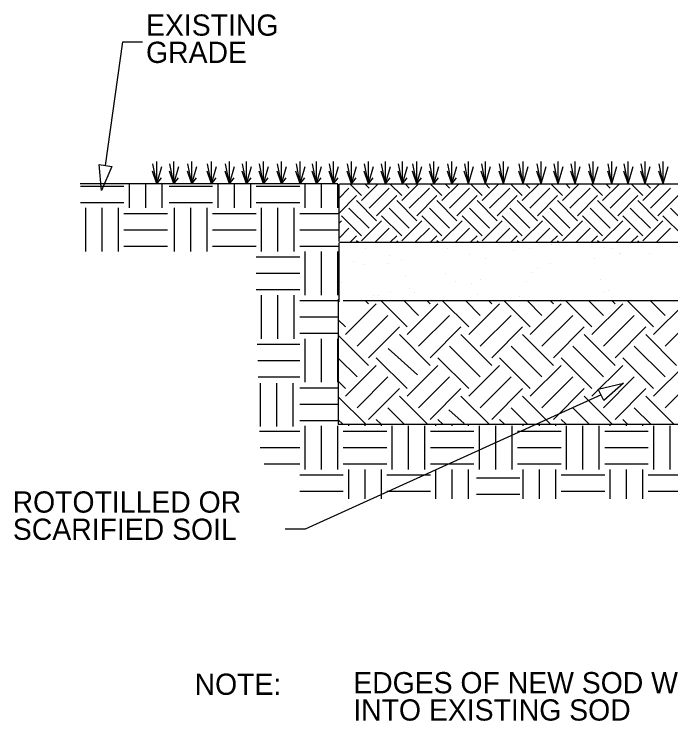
# Model space of a CAD drawing. Extents: x 10146.6 to 10186.7, y 9955.2 to 10001.8.
# Drawn here: x 10146.58 to 10168.25, y 9978.52 to 10001.83 of the extents above; entities that cross this region are included whole.
import ezdxf

# ---------------------------------------------------------------- set-up
doc = ezdxf.new("R2010")
doc.units = 0
for name, color, linetype in [('Default', 7, 'Continuous'), ('G-DETL-OTLN', 7, 'Continuous'), ('G-DETL-PATT', 7, 'Continuous'), ('G-DETL-TEXT', 7, 'Continuous')]:
    doc.layers.add(name, color=color, linetype=linetype)

# ---------------------------------------------------------------- blocks, each defined once
blk = doc.blocks.new('TERARR')
at = {"layer": 'Default'}
blk.add_lwpolyline([(-0.667, 0.167), (0, 0), (-0.667, -0.167)], close=True, dxfattribs=at)

msp = doc.modelspace()

# ---------------------------------------------------------------- linework, layer by layer
at = {"layer": 'G-DETL-OTLN'}
for points in [[(10157.298, 9994.333), (10157.298, 9996.225)], [(10157.311, 9996.235), (10175.448, 9996.235)], [(10157.298, 9992.345), (10157.298, 9994.288)], [(10157.311, 9994.307), (10175.448, 9994.307)], [(10157.272, 9992.435), (10157.272, 9988.305), (10175.536, 9988.305)], [(10157.434, 9992.388), (10175.807, 9992.388)]]:
    msp.add_lwpolyline(points, dxfattribs=at)
at = {"layer": 'G-DETL-PATT'}
for p, q in [((10151.288, 9996.238), (10151.288, 9996.977)), ((10151.849, 9996.238), (10151.849, 9996.977)), ((10152.44, 9996.238), (10152.44, 9996.977)), ((10153.09, 9996.238), (10153.09, 9996.977)), ((10153.684, 9996.238), (10153.684, 9996.977)), ((10154.245, 9996.238), (10154.245, 9996.977)), ((10154.807, 9996.238), (10154.807, 9996.977)), ((10155.398, 9996.238), (10155.398, 9996.977)), ((10156.018, 9996.238), (10156.018, 9996.977)), ((10156.551, 9996.238), (10156.551, 9996.977)), ((10157.113, 9996.238), (10157.113, 9996.977)), ((10157.704, 9996.238), (10157.704, 9996.977)), ((10158.265, 9996.238), (10158.265, 9996.977)), ((10158.827, 9996.238), (10158.827, 9996.977)), ((10159.389, 9996.238), (10159.389, 9996.977)), ((10159.86, 9996.238), (10159.86, 9996.977)), ((10160.422, 9996.238), (10160.422, 9996.977)), ((10161.016, 9996.238), (10161.016, 9996.977)), ((10161.572, 9996.238), (10161.572, 9996.977)), ((10162.134, 9996.238), (10162.134, 9996.977)), ((10162.725, 9996.238), (10162.725, 9996.977)), ((10163.375, 9996.238), (10163.375, 9996.977)), ((10163.968, 9996.238), (10163.968, 9996.977)), ((10164.53, 9996.238), (10164.53, 9996.977)), ((10165.092, 9996.238), (10165.092, 9996.977)), ((10165.683, 9996.238), (10165.683, 9996.977)), ((10166.303, 9996.238), (10166.303, 9996.977)), ((10166.836, 9996.238), (10166.836, 9996.977)), ((10167.397, 9996.238), (10167.397, 9996.977)), ((10167.988, 9996.238), (10167.988, 9996.977)), ((10151.288, 9996.238), (10151.158, 9996.901)), ((10151.288, 9996.238), (10151.454, 9996.811)), ((10151.849, 9996.238), (10151.72, 9996.901)), ((10151.849, 9996.238), (10152.015, 9996.811)), ((10152.44, 9996.238), (10152.311, 9996.901)), ((10152.44, 9996.238), (10152.607, 9996.811)), ((10153.09, 9996.238), (10152.961, 9996.901)), ((10153.09, 9996.238), (10153.256, 9996.811)), ((10153.684, 9996.238), (10153.554, 9996.901)), ((10153.684, 9996.238), (10153.85, 9996.811)), ((10154.245, 9996.238), (10154.116, 9996.901)), ((10154.245, 9996.238), (10154.411, 9996.811)), ((10154.807, 9996.238), (10154.678, 9996.901)), ((10154.807, 9996.238), (10154.973, 9996.811)), ((10155.398, 9996.238), (10155.269, 9996.901)), ((10155.398, 9996.238), (10155.564, 9996.811)), ((10156.018, 9996.238), (10155.889, 9996.901)), ((10156.018, 9996.238), (10156.185, 9996.811)), ((10156.551, 9996.238), (10156.421, 9996.901)), ((10156.551, 9996.238), (10156.717, 9996.811)), ((10157.113, 9996.238), (10156.983, 9996.901)), ((10157.113, 9996.238), (10157.279, 9996.811)), ((10157.704, 9996.238), (10157.574, 9996.901)), ((10157.704, 9996.238), (10157.87, 9996.811)), ((10158.265, 9996.238), (10158.136, 9996.901)), ((10158.265, 9996.238), (10158.432, 9996.811)), ((10158.827, 9996.238), (10158.698, 9996.901)), ((10158.827, 9996.238), (10158.993, 9996.811)), ((10159.389, 9996.238), (10159.259, 9996.901)), ((10159.389, 9996.238), (10159.555, 9996.811)), ((10159.86, 9996.238), (10159.731, 9996.901)), ((10159.86, 9996.238), (10160.026, 9996.811)), ((10160.422, 9996.238), (10160.293, 9996.901)), ((10160.422, 9996.238), (10160.588, 9996.811)), ((10161.016, 9996.238), (10160.886, 9996.901)), ((10161.016, 9996.238), (10161.182, 9996.811)), ((10161.572, 9996.238), (10161.443, 9996.901)), ((10161.572, 9996.238), (10161.738, 9996.811)), ((10162.134, 9996.238), (10162.005, 9996.901)), ((10162.134, 9996.238), (10162.3, 9996.811)), ((10162.725, 9996.238), (10162.596, 9996.901)), ((10162.725, 9996.238), (10162.891, 9996.811)), ((10163.375, 9996.238), (10163.245, 9996.901)), ((10163.375, 9996.238), (10163.541, 9996.811)), ((10163.968, 9996.238), (10163.839, 9996.901)), ((10163.968, 9996.238), (10164.134, 9996.811)), ((10164.53, 9996.238), (10164.401, 9996.901)), ((10164.53, 9996.238), (10164.696, 9996.811)), ((10165.092, 9996.238), (10164.962, 9996.901)), ((10165.092, 9996.238), (10165.258, 9996.811)), ((10165.683, 9996.238), (10165.553, 9996.901)), ((10165.683, 9996.238), (10165.849, 9996.811)), ((10166.303, 9996.238), (10166.174, 9996.901)), ((10166.303, 9996.238), (10166.469, 9996.811)), ((10166.836, 9996.238), (10166.706, 9996.901)), ((10166.836, 9996.238), (10167.002, 9996.811)), ((10167.397, 9996.238), (10167.268, 9996.901)), ((10167.397, 9996.238), (10167.563, 9996.811)), ((10167.988, 9996.238), (10167.859, 9996.901)), ((10167.988, 9996.238), (10168.155, 9996.811)), ((10151.288, 9996.238), (10151.146, 9996.657)), ((10151.849, 9996.238), (10151.708, 9996.657)), ((10152.44, 9996.238), (10152.299, 9996.657)), ((10153.09, 9996.238), (10152.948, 9996.657)), ((10153.684, 9996.238), (10153.542, 9996.657)), ((10154.245, 9996.238), (10154.104, 9996.657)), ((10154.807, 9996.238), (10154.665, 9996.657)), ((10155.398, 9996.238), (10155.256, 9996.657)), ((10156.018, 9996.238), (10155.877, 9996.657)), ((10156.551, 9996.238), (10156.409, 9996.657)), ((10157.113, 9996.238), (10156.971, 9996.657)), ((10157.704, 9996.238), (10157.562, 9996.657)), ((10158.265, 9996.238), (10158.124, 9996.657)), ((10158.827, 9996.238), (10158.686, 9996.657)), ((10159.389, 9996.238), (10159.247, 9996.657)), ((10159.86, 9996.238), (10159.719, 9996.657)), ((10160.422, 9996.238), (10160.28, 9996.657)), ((10161.016, 9996.238), (10160.874, 9996.657)), ((10161.572, 9996.238), (10161.431, 9996.657)), ((10162.134, 9996.238), (10161.992, 9996.657)), ((10162.725, 9996.238), (10162.584, 9996.657)), ((10163.375, 9996.238), (10163.233, 9996.657)), ((10163.968, 9996.238), (10163.827, 9996.657)), ((10164.53, 9996.238), (10164.388, 9996.657)), ((10165.092, 9996.238), (10164.95, 9996.657)), ((10165.683, 9996.238), (10165.541, 9996.657)), ((10166.303, 9996.238), (10166.162, 9996.657)), ((10166.836, 9996.238), (10166.694, 9996.657)), ((10167.397, 9996.238), (10167.256, 9996.657)), ((10167.988, 9996.238), (10167.847, 9996.657)), ((10151.288, 9996.238), (10151.442, 9996.439)), ((10151.849, 9996.238), (10152.003, 9996.439)), ((10152.44, 9996.238), (10152.594, 9996.439)), ((10153.09, 9996.238), (10153.244, 9996.439)), ((10153.684, 9996.238), (10153.837, 9996.439)), ((10154.245, 9996.238), (10154.399, 9996.439)), ((10154.807, 9996.238), (10154.961, 9996.439)), ((10155.398, 9996.238), (10155.552, 9996.439)), ((10156.018, 9996.238), (10156.172, 9996.439)), ((10156.551, 9996.238), (10156.705, 9996.439)), ((10157.113, 9996.238), (10157.267, 9996.439)), ((10157.704, 9996.238), (10157.858, 9996.439)), ((10158.265, 9996.238), (10158.419, 9996.439)), ((10158.827, 9996.238), (10158.981, 9996.439)), ((10159.389, 9996.238), (10159.543, 9996.439)), ((10159.86, 9996.238), (10160.014, 9996.439)), ((10160.422, 9996.238), (10160.576, 9996.439)), ((10161.016, 9996.238), (10161.169, 9996.439)), ((10157.258, 9996.238), (10148.757, 9996.238)), ((10148.764, 9996.159), (10150.201, 9996.159)), ((10150.381, 9995.44), (10150.381, 9996.238)), ((10150.92, 9995.44), (10150.92, 9996.238)), ((10151.459, 9995.44), (10151.459, 9996.238)), ((10151.688, 9996.159), (10153.125, 9996.159)), ((10153.305, 9995.44), (10153.305, 9996.238)), ((10153.844, 9995.44), (10153.844, 9996.238)), ((10154.383, 9995.44), (10154.383, 9996.238)), ((10154.563, 9996.159), (10156, 9996.159)), ((10156.18, 9995.44), (10156.18, 9996.238)), ((10156.719, 9995.44), (10156.719, 9996.238)), ((10157.258, 9995.44), (10157.258, 9996.238)), ((10157.298, 9995.768), (10157.626, 9996.096)), ((10158.041, 9995.848), (10157.653, 9996.235)), ((10158.041, 9995.682), (10158.594, 9996.235)), ((10158.289, 9996.096), (10158.15, 9996.235)), ((10158.289, 9995.433), (10158.952, 9996.096)), ((10159.367, 9995.848), (10158.979, 9996.235)), ((10159.367, 9995.682), (10159.92, 9996.235)), ((10159.615, 9996.096), (10159.476, 9996.235)), ((10159.615, 9995.433), (10160.278, 9996.096)), ((10160.692, 9995.848), (10160.305, 9996.235)), ((10160.692, 9995.682), (10161.246, 9996.235)), ((10160.941, 9996.096), (10160.802, 9996.235)), ((10160.941, 9995.433), (10161.604, 9996.096)), ((10162.018, 9995.848), (10161.631, 9996.235)), ((10162.018, 9995.682), (10162.571, 9996.235)), ((10162.267, 9996.096), (10162.128, 9996.235)), ((10162.267, 9995.433), (10162.93, 9996.096)), ((10163.344, 9995.848), (10162.956, 9996.235)), ((10163.344, 9995.682), (10163.897, 9996.235)), ((10163.593, 9996.096), (10163.454, 9996.235)), ((10163.593, 9995.433), (10164.256, 9996.096)), ((10164.67, 9995.848), (10164.282, 9996.235)), ((10164.67, 9995.682), (10165.223, 9996.235)), ((10164.918, 9996.096), (10164.78, 9996.235)), ((10164.918, 9995.433), (10165.581, 9996.096)), ((10165.996, 9995.848), (10165.608, 9996.235)), ((10165.996, 9995.682), (10166.549, 9996.235)), ((10166.244, 9996.096), (10166.105, 9996.235)), ((10166.244, 9995.433), (10166.907, 9996.096)), ((10167.322, 9995.848), (10166.934, 9996.235)), ((10167.322, 9995.682), (10167.875, 9996.235)), ((10167.57, 9996.096), (10167.431, 9996.235)), ((10167.57, 9995.433), (10168.233, 9996.096)), ((10157.298, 9995.27), (10157.875, 9995.848)), ((10158.538, 9995.185), (10159.201, 9995.848)), ((10159.864, 9995.185), (10160.527, 9995.848)), ((10161.19, 9995.185), (10161.852, 9995.848)), ((10162.515, 9995.185), (10163.178, 9995.848)), ((10163.841, 9995.185), (10164.504, 9995.848)), ((10165.167, 9995.185), (10165.83, 9995.848)), ((10166.493, 9995.185), (10167.156, 9995.848)), ((10167.819, 9995.185), (10168.482, 9995.848)), ((10148.764, 9995.62), (10150.201, 9995.62)), ((10151.688, 9995.62), (10153.125, 9995.62)), ((10154.563, 9995.62), (10156, 9995.62)), ((10158.538, 9995.019), (10157.875, 9995.682)), ((10159.864, 9995.019), (10159.201, 9995.682)), ((10161.19, 9995.019), (10160.527, 9995.682)), ((10162.515, 9995.019), (10161.852, 9995.682)), ((10163.841, 9995.019), (10163.178, 9995.682)), ((10165.167, 9995.019), (10164.504, 9995.682)), ((10166.493, 9995.019), (10165.83, 9995.682)), ((10167.819, 9995.019), (10167.156, 9995.682)), ((10148.943, 9994.003), (10148.943, 9995.44)), ((10149.482, 9994.003), (10149.482, 9995.44)), ((10150.021, 9994.003), (10150.021, 9995.44)), ((10151.868, 9994.003), (10151.868, 9995.44)), ((10152.407, 9994.003), (10152.407, 9995.44)), ((10152.946, 9994.003), (10152.946, 9995.44)), ((10154.743, 9994.003), (10154.743, 9995.44)), ((10155.282, 9994.003), (10155.282, 9995.44)), ((10155.821, 9994.003), (10155.821, 9995.44)), ((10158.289, 9994.771), (10157.626, 9995.433)), ((10159.615, 9994.771), (10158.952, 9995.433)), ((10160.941, 9994.771), (10160.278, 9995.433)), ((10162.267, 9994.771), (10161.604, 9995.433)), ((10163.593, 9994.771), (10162.93, 9995.433)), ((10164.918, 9994.771), (10164.256, 9995.433)), ((10166.244, 9994.771), (10165.581, 9995.433)), ((10167.57, 9994.771), (10166.907, 9995.433)), ((10168.896, 9994.771), (10168.233, 9995.433)), ((10150.201, 9995.26), (10151.639, 9995.26)), ((10153.125, 9995.26), (10154.563, 9995.26)), ((10156, 9995.26), (10157.298, 9995.26)), ((10158.041, 9994.522), (10157.378, 9995.185)), ((10159.367, 9994.522), (10158.704, 9995.185)), ((10160.692, 9994.522), (10160.029, 9995.185)), ((10162.018, 9994.522), (10161.355, 9995.185)), ((10163.344, 9994.522), (10162.681, 9995.185)), ((10164.67, 9994.522), (10164.007, 9995.185)), ((10165.996, 9994.522), (10165.333, 9995.185)), ((10167.322, 9994.522), (10166.659, 9995.185)), ((10168.647, 9994.522), (10167.984, 9995.185)), ((10157.298, 9994.939), (10157.378, 9995.019)), ((10158.041, 9994.356), (10158.704, 9995.019)), ((10159.367, 9994.356), (10160.029, 9995.019)), ((10160.692, 9994.356), (10161.355, 9995.019)), ((10162.018, 9994.356), (10162.681, 9995.019)), ((10163.344, 9994.356), (10164.007, 9995.019)), ((10164.67, 9994.356), (10165.333, 9995.019)), ((10165.996, 9994.356), (10166.659, 9995.019)), ((10167.322, 9994.356), (10167.984, 9995.019)), ((10150.201, 9994.721), (10151.639, 9994.721)), ((10153.125, 9994.721), (10154.563, 9994.721)), ((10156, 9994.721), (10157.298, 9994.721)), ((10157.298, 9994.442), (10157.626, 9994.771)), ((10158.488, 9994.307), (10158.952, 9994.771)), ((10159.814, 9994.307), (10160.278, 9994.771)), ((10161.14, 9994.307), (10161.604, 9994.771)), ((10162.466, 9994.307), (10162.93, 9994.771)), ((10163.792, 9994.307), (10164.256, 9994.771)), ((10165.117, 9994.307), (10165.581, 9994.771)), ((10166.443, 9994.307), (10166.907, 9994.771)), ((10167.769, 9994.307), (10168.233, 9994.771)), ((10157.66, 9994.307), (10157.875, 9994.522)), ((10158.985, 9994.307), (10159.201, 9994.522)), ((10160.311, 9994.307), (10160.527, 9994.522)), ((10161.637, 9994.307), (10161.852, 9994.522)), ((10162.963, 9994.307), (10163.178, 9994.522)), ((10164.289, 9994.307), (10164.504, 9994.522)), ((10165.615, 9994.307), (10165.83, 9994.522)), ((10166.94, 9994.307), (10167.156, 9994.522)), ((10150.201, 9994.182), (10151.639, 9994.182)), ((10153.125, 9994.182), (10154.563, 9994.182)), ((10156, 9994.182), (10157.298, 9994.182)), ((10157.925, 9994.307), (10157.875, 9994.356)), ((10159.251, 9994.307), (10159.201, 9994.356)), ((10160.576, 9994.307), (10160.527, 9994.356)), ((10161.902, 9994.307), (10161.852, 9994.356)), ((10163.228, 9994.307), (10163.178, 9994.356)), ((10164.297, 9994.25), (10164.297, 9994.25)), ((10164.554, 9994.307), (10164.504, 9994.356)), ((10165.88, 9994.307), (10165.83, 9994.356)), ((10166.899, 9994.259), (10166.899, 9994.259)), ((10167.205, 9994.307), (10167.156, 9994.356)), ((10156.18, 9992.565), (10156.18, 9994.003)), ((10156.719, 9992.565), (10156.719, 9994.003)), ((10157.258, 9992.565), (10157.258, 9994.003)), ((10158.175, 9994.096), (10158.175, 9994.096)), ((10160.875, 9994.096), (10160.875, 9994.096)), ((10163.041, 9994.039), (10163.041, 9994.039)), ((10163.575, 9994.096), (10163.575, 9994.096)), ((10166.065, 9994.15), (10166.065, 9994.15)), ((10166.275, 9994.096), (10166.275, 9994.096)), ((10166.554, 9993.943), (10166.554, 9993.943)), ((10166.59, 9993.942), (10166.59, 9993.942)), ((10167.53, 9993.953), (10167.53, 9993.953)), ((10154.563, 9993.823), (10156, 9993.823)), ((10158.955, 9993.858), (10158.955, 9993.858)), ((10159.351, 9993.739), (10159.351, 9993.739)), ((10161.617, 9993.921), (10161.617, 9993.921)), ((10162.139, 9993.779), (10162.139, 9993.779)), ((10165.726, 9993.757), (10165.726, 9993.757)), ((10157.789, 9993.667), (10157.789, 9993.667)), ((10158.128, 9993.576), (10158.128, 9993.576)), ((10158.938, 9993.592), (10158.938, 9993.592)), ((10163.847, 9993.483), (10163.847, 9993.483)), ((10164.279, 9993.606), (10164.279, 9993.606)), ((10154.563, 9993.284), (10156, 9993.284)), ((10160.813, 9993.294), (10160.813, 9993.294)), ((10163.662, 9993.299), (10163.662, 9993.299)), ((10159.498, 9993.218), (10159.498, 9993.218)), ((10161.139, 9993.024), (10161.139, 9993.024)), ((10161.971, 9993.086), (10161.971, 9993.086)), ((10163.498, 9993.012), (10163.498, 9993.012)), ((10165.909, 9993.086), (10165.909, 9993.086)), ((10157.38, 9992.972), (10157.38, 9992.972)), ((10159.622, 9992.776), (10159.622, 9992.776)), ((10161.659, 9992.953), (10161.659, 9992.953)), ((10154.563, 9992.745), (10156, 9992.745)), ((10154.743, 9991.128), (10154.743, 9992.565)), ((10155.282, 9991.128), (10155.282, 9992.565)), ((10155.821, 9991.128), (10155.821, 9992.565)), ((10158.432, 9992.565), (10158.432, 9992.565)), ((10158.585, 9992.548), (10158.585, 9992.548)), ((10158.986, 9992.686), (10158.986, 9992.686)), ((10159.793, 9992.646), (10159.793, 9992.646)), ((10161.863, 9992.58), (10161.863, 9992.58)), ((10166.032, 9992.649), (10166.032, 9992.649)), ((10166.183, 9992.729), (10166.183, 9992.729)), ((10156, 9992.385), (10157.298, 9992.385)), ((10158.273, 9992.279), (10158.164, 9992.388)), ((10159.543, 9991.517), (10158.672, 9992.388)), ((10159.925, 9991.898), (10159.434, 9992.388)), ((10160.306, 9992.279), (10160.197, 9992.388)), ((10161.576, 9991.517), (10160.705, 9992.388)), ((10161.957, 9991.898), (10161.467, 9992.388)), ((10162.339, 9992.279), (10162.23, 9992.388)), ((10163.609, 9991.517), (10162.738, 9992.388)), ((10163.268, 9992.525), (10163.268, 9992.525)), ((10163.99, 9991.898), (10163.5, 9992.388)), ((10164.372, 9992.279), (10164.263, 9992.388)), ((10164.591, 9992.432), (10164.591, 9992.432)), ((10165.642, 9991.517), (10164.771, 9992.388)), ((10166.023, 9991.898), (10165.533, 9992.388)), ((10166.404, 9992.279), (10166.296, 9992.388)), ((10167.675, 9991.517), (10166.804, 9992.388)), ((10168.056, 9991.898), (10167.566, 9992.388)), ((10157.51, 9991.263), (10158.527, 9992.279)), ((10159.543, 9991.263), (10160.56, 9992.279)), ((10161.576, 9991.263), (10162.593, 9992.279)), ((10163.609, 9991.263), (10164.626, 9992.279)), ((10165.642, 9991.263), (10166.659, 9992.279)), ((10167.675, 9991.263), (10168.692, 9992.279)), ((10156, 9991.846), (10157.272, 9991.846)), ((10157.892, 9990.881), (10158.908, 9991.898)), ((10159.925, 9990.881), (10160.941, 9991.898)), ((10161.957, 9990.881), (10162.974, 9991.898)), ((10163.99, 9990.881), (10165.007, 9991.898)), ((10166.023, 9990.881), (10167.04, 9991.898)), ((10168.056, 9990.881), (10169.073, 9991.898)), ((10157.51, 9991.517), (10157.272, 9991.755)), ((10158.273, 9990.5), (10159.289, 9991.517)), ((10160.306, 9990.5), (10161.322, 9991.517)), ((10162.339, 9990.5), (10163.355, 9991.517)), ((10164.372, 9990.5), (10165.388, 9991.517)), ((10166.404, 9990.5), (10167.421, 9991.517)), ((10156, 9991.307), (10157.272, 9991.307)), ((10158.273, 9990.246), (10157.272, 9991.247)), ((10160.306, 9990.246), (10159.289, 9991.263)), ((10162.339, 9990.246), (10161.322, 9991.263)), ((10164.372, 9990.246), (10163.355, 9991.263)), ((10166.404, 9990.246), (10165.388, 9991.263)), ((10168.437, 9990.246), (10167.421, 9991.263)), ((10154.6, 9990.948), (10156, 9990.948)), ((10156.18, 9989.69), (10156.18, 9991.128)), ((10156.719, 9989.69), (10156.719, 9991.128)), ((10157.258, 9989.69), (10157.258, 9991.128)), ((10158.924, 9990.806), (10159.886, 9989.935)), ((10161.957, 9989.865), (10160.941, 9990.881)), ((10163.99, 9989.865), (10162.974, 9990.881)), ((10166.023, 9989.865), (10165.007, 9990.881)), ((10168.056, 9989.865), (10167.04, 9990.881)), ((10157.892, 9989.865), (10157.272, 9990.485)), ((10159.543, 9989.484), (10158.527, 9990.5)), ((10161.576, 9989.484), (10160.56, 9990.5)), ((10163.609, 9989.484), (10162.593, 9990.5)), ((10165.642, 9989.484), (10164.626, 9990.5)), ((10167.675, 9989.484), (10166.659, 9990.5)), ((10154.614, 9990.409), (10156, 9990.409)), ((10157.51, 9989.23), (10158.527, 9990.246)), ((10159.543, 9989.23), (10160.56, 9990.246)), ((10161.576, 9989.23), (10162.593, 9990.246)), ((10163.609, 9989.23), (10164.626, 9990.246)), ((10165.642, 9989.23), (10166.659, 9990.246)), ((10167.675, 9989.23), (10168.692, 9990.246)), ((10154.629, 9989.87), (10156, 9989.87)), ((10157.892, 9988.848), (10158.908, 9989.865)), ((10159.925, 9988.848), (10160.941, 9989.865)), ((10161.957, 9988.848), (10162.974, 9989.865)), ((10163.99, 9988.848), (10165.007, 9989.865)), ((10166.023, 9988.848), (10167.04, 9989.865)), ((10168.056, 9988.848), (10169.073, 9989.865)), ((10154.702, 9988.229), (10154.702, 9989.666)), ((10155.241, 9988.229), (10155.241, 9989.666)), ((10155.78, 9988.229), (10155.78, 9989.666)), ((10157.51, 9989.484), (10157.272, 9989.722)), ((10156, 9989.51), (10157.272, 9989.51)), ((10158.273, 9988.467), (10159.289, 9989.484)), ((10160.306, 9988.467), (10161.322, 9989.484)), ((10162.339, 9988.467), (10163.355, 9989.484)), ((10164.372, 9988.467), (10165.388, 9989.484)), ((10166.404, 9988.467), (10167.421, 9989.484)), ((10158.181, 9988.305), (10157.272, 9989.214)), ((10160.214, 9988.305), (10159.289, 9989.23)), ((10162.247, 9988.305), (10161.322, 9989.23)), ((10164.28, 9988.305), (10163.355, 9989.23)), ((10166.313, 9988.305), (10165.388, 9989.23)), ((10168.346, 9988.305), (10167.421, 9989.23)), ((10156, 9988.971), (10157.272, 9988.971)), ((10159.451, 9988.305), (10158.908, 9988.848)), ((10163.517, 9988.305), (10162.974, 9988.848)), ((10165.55, 9988.305), (10165.007, 9988.848)), ((10167.583, 9988.305), (10167.04, 9988.848)), ((10160.926, 9988.782), (10161.428, 9988.327)), ((10156, 9988.432), (10157.272, 9988.432)), ((10157.419, 9988.305), (10157.272, 9988.452)), ((10158.689, 9988.305), (10158.527, 9988.467)), ((10160.722, 9988.305), (10160.56, 9988.467)), ((10162.755, 9988.305), (10162.593, 9988.467)), ((10164.788, 9988.305), (10164.626, 9988.467)), ((10166.821, 9988.305), (10166.659, 9988.467)), ((10156.18, 9986.815), (10156.18, 9988.253)), ((10156.719, 9986.815), (10156.719, 9988.253)), ((10157.258, 9986.815), (10157.258, 9988.253)), ((10157.618, 9988.253), (10157.618, 9988.305)), ((10158.157, 9988.253), (10158.157, 9988.305)), ((10158.696, 9988.253), (10158.696, 9988.305)), ((10159.055, 9986.815), (10159.055, 9988.253)), ((10159.594, 9986.815), (10159.594, 9988.253)), ((10160.133, 9986.815), (10160.133, 9988.253)), ((10160.493, 9988.253), (10160.493, 9988.305)), ((10161.032, 9988.253), (10161.032, 9988.305)), ((10161.571, 9988.253), (10161.571, 9988.305)), ((10161.93, 9986.815), (10161.93, 9988.253)), ((10162.469, 9986.815), (10162.469, 9988.253)), ((10163.008, 9986.815), (10163.008, 9988.253)), ((10163.368, 9988.253), (10163.368, 9988.305)), ((10163.907, 9988.253), (10163.907, 9988.305)), ((10164.446, 9988.253), (10164.446, 9988.305)), ((10164.805, 9986.815), (10164.805, 9988.253)), ((10165.344, 9986.815), (10165.344, 9988.253)), ((10165.883, 9986.815), (10165.883, 9988.253)), ((10166.243, 9988.253), (10166.243, 9988.305)), ((10166.782, 9988.253), (10166.782, 9988.305)), ((10167.321, 9988.253), (10167.321, 9988.305)), ((10167.68, 9986.815), (10167.68, 9988.253)), ((10168.219, 9986.815), (10168.219, 9988.253)), ((10154.679, 9988.073), (10156, 9988.073)), ((10157.438, 9988.073), (10158.875, 9988.073)), ((10160.313, 9988.073), (10161.75, 9988.073)), ((10163.188, 9988.073), (10164.625, 9988.073)), ((10166.063, 9988.073), (10167.5, 9988.073)), ((10154.694, 9987.534), (10156, 9987.534)), ((10157.438, 9987.534), (10158.875, 9987.534)), ((10160.313, 9987.534), (10161.75, 9987.534)), ((10163.188, 9987.534), (10164.625, 9987.534)), ((10166.063, 9987.534), (10167.5, 9987.534)), ((10154.831, 9986.995), (10156, 9986.995)), ((10157.438, 9986.995), (10158.875, 9986.995)), ((10160.313, 9986.995), (10161.75, 9986.995)), ((10163.188, 9986.995), (10164.625, 9986.995)), ((10166.063, 9986.995), (10167.5, 9986.995)), ((10157.618, 9985.843), (10157.618, 9986.815)), ((10158.157, 9985.843), (10158.157, 9986.815)), ((10158.696, 9985.843), (10158.696, 9986.815)), ((10160.493, 9985.843), (10160.493, 9986.815)), ((10161.032, 9985.843), (10161.032, 9986.815)), ((10161.571, 9985.843), (10161.571, 9986.815)), ((10163.368, 9985.843), (10163.368, 9986.815)), ((10163.907, 9985.843), (10163.907, 9986.815)), ((10164.446, 9985.843), (10164.446, 9986.815)), ((10166.243, 9985.843), (10166.243, 9986.815)), ((10166.782, 9985.843), (10166.782, 9986.815)), ((10167.321, 9985.843), (10167.321, 9986.815)), ((10156, 9986.635), (10157.438, 9986.635)), ((10158.875, 9986.635), (10160.313, 9986.635)), ((10161.829, 9986.538), (10163.266, 9986.538)), ((10164.625, 9986.635), (10166.063, 9986.635)), ((10167.5, 9986.635), (10168.938, 9986.635)), ((10156, 9986.096), (10157.438, 9986.096)), ((10158.875, 9986.096), (10160.313, 9986.096)), ((10164.625, 9986.096), (10166.063, 9986.096)), ((10167.5, 9986.096), (10168.938, 9986.096)), ((10161.829, 9985.999), (10163.266, 9985.999))]:
    msp.add_line(p, q, dxfattribs=at)
for points in [[(10149.594, 9996.836), (10150.16, 10000.924), (10150.816, 10000.924)], [(10165.944, 9989.277), (10156.179, 9984.849), (10155.523, 9984.849)]]:
    msp.add_lwpolyline(points, dxfattribs=at)

# ---------------------------------------------------------------- block references
for p, xscale, yscale, rotation in [((10149.459, 9996.014), 1.2500000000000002, 1.25, -99.35282054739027), ((10166.685, 9989.658), 1.2499999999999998, 1.2499999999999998, 27.186862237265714)]:
    msp.add_blockref('TERARR', p, dxfattribs=dict(at, xscale=xscale, yscale=yscale, rotation=rotation))

# ---------------------------------------------------------------- texts
at = {"layer": 'G-DETL-TEXT'}
for s, p in [('EXISTING', (10150.93, 10001.123)), ('GRADE', (10150.93, 10000.224)), ('ROTOTILLED OR', (10146.527, 9985.391)), ('SCARIFIED SOIL', (10146.536, 9984.492)), ('NOTE:', (10152.532, 9979.38)), ('EDGES OF NEW SOD WILL BE CUT ', (10157.767, 9979.431)), ('INTO EXISTING SOD', (10157.767, 9978.531))]:
    msp.add_text(s, height=0.7, dxfattribs=at).set_placement(p)

doc.saveas('drawing.dxf')
